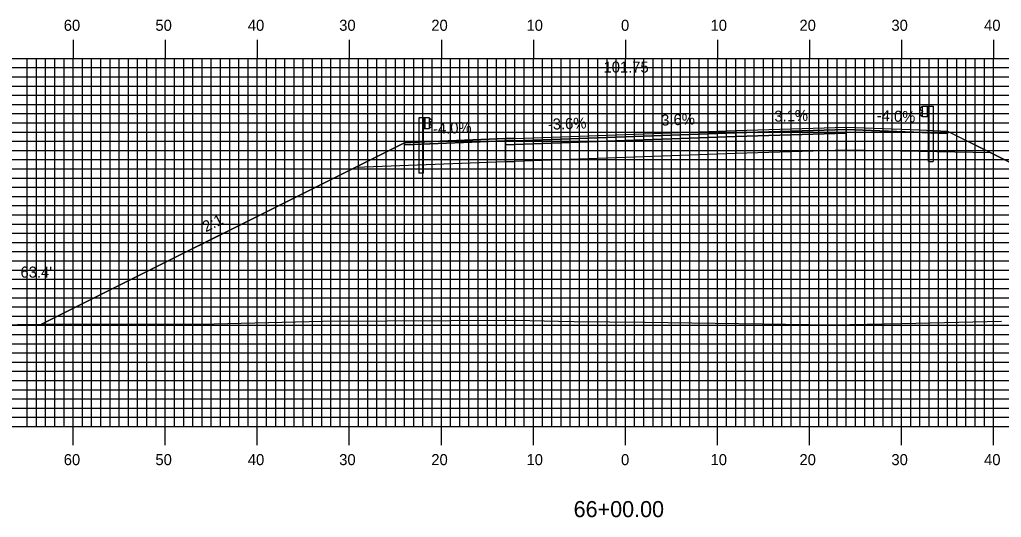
# Model space of a CAD drawing. Extents: x 1759036 to 1759380, y 442591 to 442811.
# Drawn here: x 1759136.3 to 1759243, y 442658.8 to 442712.9 of the extents above; entities that cross this region are included whole.
import ezdxf

# ---------------------------------------------------------------- set-up
doc = ezdxf.new("R2010")
doc.units = 0
for name, color, linetype in [('ANNOTATION', 7, 'Continuous'), ('D_Guardrail_Beam_Lt', 7, 'Continuous'), ('D_Guardrail_Beam_Rt', 7, 'Continuous'), ('D_Roadway_Centerline', 7, 'Continuous'), ('D_Roadway_Centerline_Text', 7, 'Continuous'), ('D_Roadway_Edge_Shoulder', 7, 'Continuous'), ('D_Roadway_Edge_TW', 7, 'Continuous'), ('D_Roadway_Pavement', 7, 'Continuous'), ('D_Roadway_SlopeLines', 7, 'Continuous'), ('D_Roadway_SubGrade', 7, 'Continuous'), ('D_Text_Standard', 7, 'Continuous'), ('H_V ANNOTATION', 7, 'Continuous'), ('MAJOR', 7, 'Continuous'), ('MINOR', 7, 'Continuous'), ('S_Roadway_Centerline', 7, 'Continuous')]:
    doc.layers.add(name, color=color, linetype=linetype)

msp = doc.modelspace()

# ---------------------------------------------------------------- linework, layer by layer
at = {"layer": 'D_Guardrail_Beam_Lt'}
for p, q in [((1759179.71, 442702.21), (1759179.71, 442696.21)), ((1759180.19, 442702.21), (1759179.71, 442702.21)), ((1759180.87, 442702.21), (1759180.19, 442702.21)), ((1759180.19, 442702.21), (1759180.19, 442701.04)), ((1759180.25, 442702.21), (1759180.25, 442701.04)), ((1759180.35, 442702.21), (1759180.35, 442701.04)), ((1759180.87, 442701.04), (1759180.87, 442702.21)), ((1759180.87, 442702.13), (1759180.95, 442702.11)), ((1759180.88, 442701.66), (1759180.88, 442701.59)), ((1759181.11, 442701.86), (1759180.91, 442701.73)), ((1759180.96, 442702.11), (1759181.11, 442702.01)), ((1759180.19, 442701.04), (1759180.87, 442701.04)), ((1759180.21, 442696.21), (1759180.21, 442701.04)), ((1759180.95, 442701.14), (1759180.87, 442701.13)), ((1759180.91, 442701.53), (1759181.11, 442701.39)), ((1759181.11, 442701.25), (1759180.96, 442701.15)), ((1759180.21, 442696.21), (1759179.71, 442696.21))]:
    msp.add_line(p, q, dxfattribs=at)
for centre, major_axis, start_param, end_param in [((1759180.96, 442701.66), (-0.0789, 0), 5.323254, 6.283185), ((1759180.96, 442701.59), (-0.0789, 0), 6.283185, 7.243116), ((1759180.94, 442702.07), (0.0417, 0), 0.959931, 1.376053), ((1759181.06, 442701.93), (0.0877, 0), 5.323254, 7.243116), ((1759180.94, 442701.18), (0.0417, 0), 4.907132, 5.323254), ((1759181.06, 442701.32), (0.0877, 0), 5.323254, 7.243116)]:
    msp.add_ellipse(centre, major_axis=major_axis, ratio=0.995501, start_param=start_param, end_param=end_param, dxfattribs=at)
at = {"layer": 'D_Guardrail_Beam_Rt'}
for p, q in [((1759234.34, 442703.37), (1759234.2, 442703.27)), ((1759234.2, 442703.13), (1759234.39, 442702.99)), ((1759234.39, 442702.8), (1759234.2, 442702.66)), ((1759234.43, 442703.39), (1759234.36, 442703.38)), ((1759234.43, 442703.48), (1759235.12, 442703.48)), ((1759234.43, 442702.31), (1759234.43, 442703.48)), ((1759234.43, 442702.93), (1759234.43, 442702.86)), ((1759234.95, 442703.48), (1759234.95, 442702.31)), ((1759235.06, 442703.48), (1759235.06, 442702.31)), ((1759235.12, 442703.48), (1759235.59, 442703.48)), ((1759235.12, 442703.48), (1759235.12, 442702.31)), ((1759235.59, 442703.48), (1759235.59, 442697.48)), ((1759234.2, 442702.52), (1759234.34, 442702.42)), ((1759234.36, 442702.41), (1759234.43, 442702.39)), ((1759235.12, 442702.31), (1759234.43, 442702.31)), ((1759235.1, 442697.48), (1759235.1, 442702.31)), ((1759235.1, 442697.48), (1759235.59, 442697.48))]:
    msp.add_line(p, q, dxfattribs=at)
for centre, major_axis, start_param, end_param in [((1759234.25, 442703.2), (-0.0877, 0), 5.323254, 7.243116), ((1759234.25, 442702.59), (-0.0877, 0), 5.323254, 7.243116), ((1759234.37, 442703.34), (-0.0417, 0), 4.907132, 5.323254), ((1759234.35, 442702.93), (0.0789, 0), 0, 0.959931), ((1759234.35, 442702.86), (0.0789, 0), 5.323254, 6.283185), ((1759234.37, 442702.45), (-0.0417, 0), 0.959931, 1.376053)]:
    msp.add_ellipse(centre, major_axis=major_axis, ratio=0.995501, start_param=start_param, end_param=end_param, dxfattribs=at)
at = {"layer": 'D_Roadway_Centerline'}
msp.add_lwpolyline([(1759138.72, 442679.79), (1759172.85, 442696.86), (1759178.14, 442699.51), (1759181.14, 442699.63), (1759189.14, 442699.95), (1759190.16, 442699.98), (1759202.16, 442700.41), (1759214.16, 442700.85), (1759226.16, 442701.21), (1759234.16, 442700.89), (1759237.16, 442700.77), (1759241.91, 442698.4), (1759278.21, 442680.25)], dxfattribs=at)
at = {"layer": 'D_Roadway_Edge_Shoulder'}
for points in [[(1759226.16, 442701.21), (1759234.16, 442700.89), (1759234.16, 442700.89), (1759237.16, 442700.77), (1759237.16, 442700.52), (1759226.16, 442700.96)], [(1759189.14, 442699.95), (1759181.14, 442699.63), (1759181.14, 442699.63), (1759178.14, 442699.51), (1759178.14, 442699.26), (1759189.14, 442699.7)]]:
    msp.add_lwpolyline(points, close=True, dxfattribs=at)
at = {"layer": 'D_Roadway_Edge_TW'}
for points in [[(1759190.16, 442699.73), (1759190.16, 442699.98), (1759202.16, 442700.41), (1759214.16, 442700.85), (1759214.16, 442700.6), (1759202.16, 442700.16)], [(1759214.16, 442700.85), (1759226.16, 442701.21), (1759226.16, 442700.96), (1759214.16, 442700.6)], [(1759190.16, 442699.98), (1759189.14, 442699.95), (1759189.14, 442699.7), (1759190.16, 442699.73)]]:
    msp.add_lwpolyline(points, close=True, dxfattribs=at)
at = {"layer": 'D_Roadway_Pavement'}
for points in [[(1759190.16, 442699.32), (1759190.16, 442699.73), (1759202.16, 442700.16), (1759214.16, 442700.6), (1759214.16, 442700.18), (1759202.16, 442699.75)], [(1759214.16, 442700.6), (1759226.16, 442700.96), (1759226.16, 442700.55), (1759214.16, 442700.18)], [(1759190.16, 442699.73), (1759189.14, 442699.7), (1759189.14, 442699.28), (1759190.16, 442699.32)]]:
    msp.add_lwpolyline(points, close=True, dxfattribs=at)
for points in [[(1759226.16, 442700.96), (1759226.16, 442700.55)], [(1759226.16, 442700.96), (1759226.16, 442700.55)], [(1759226.16, 442700.96), (1759226.16, 442700.55)], [(1759226.16, 442700.96), (1759226.16, 442700.55)], [(1759226.16, 442700.96), (1759226.16, 442700.55)], [(1759189.14, 442699.7), (1759189.14, 442699.28)], [(1759189.14, 442699.7), (1759189.14, 442699.28)]]:
    msp.add_lwpolyline(points, dxfattribs=at)
at = {"layer": 'D_Roadway_SlopeLines'}
for points in [[(1759237.16, 442700.77), (1759278.21, 442680.25)], [(1759178.14, 442699.51), (1759138.72, 442679.79)]]:
    msp.add_lwpolyline(points, dxfattribs=at)
at = {"layer": 'D_Roadway_SubGrade'}
for points in [[(1759214.16, 442700.18), (1759226.16, 442700.55), (1759226.16, 442698.71), (1759214.16, 442698.35)], [(1759226.16, 442700.55), (1759226.16, 442700.96), (1759237.16, 442700.52), (1759237.16, 442700.77), (1759241.91, 442698.4), (1759226.16, 442698.71)], [(1759189.14, 442699.28), (1759189.14, 442699.7), (1759178.14, 442699.26), (1759178.14, 442699.51), (1759172.85, 442696.86), (1759189.14, 442697.45)], [(1759190.16, 442697.48), (1759190.16, 442699.32), (1759202.16, 442699.75), (1759214.16, 442700.18), (1759214.16, 442698.35), (1759202.16, 442697.91)], [(1759190.16, 442699.32), (1759189.14, 442699.28), (1759189.14, 442697.45), (1759190.16, 442697.48)]]:
    msp.add_lwpolyline(points, close=True, dxfattribs=at)
at = {"layer": 'MAJOR'}
for p, q in [((1759142.16, 442710.67), (1759142.16, 442708.67)), ((1759152.16, 442710.67), (1759152.16, 442708.67)), ((1759162.16, 442710.67), (1759162.16, 442708.67)), ((1759172.16, 442710.67), (1759172.16, 442708.67)), ((1759182.16, 442710.67), (1759182.16, 442708.67)), ((1759192.16, 442710.67), (1759192.16, 442708.67)), ((1759202.16, 442710.67), (1759202.16, 442708.67)), ((1759212.16, 442710.67), (1759212.16, 442708.67)), ((1759222.16, 442710.67), (1759222.16, 442708.67)), ((1759232.16, 442710.67), (1759232.16, 442708.67)), ((1759242.16, 442710.67), (1759242.16, 442708.67)), ((1759062.16, 442708.67), (1759342.16, 442708.67)), ((1759062.16, 442708.67), (1759342.16, 442708.67)), ((1759142.16, 442668.67), (1759142.16, 442708.67)), ((1759152.16, 442668.67), (1759152.16, 442708.67)), ((1759162.16, 442668.67), (1759162.16, 442708.67)), ((1759172.16, 442668.67), (1759172.16, 442708.67)), ((1759182.16, 442668.67), (1759182.16, 442708.67)), ((1759192.16, 442668.67), (1759192.16, 442708.67)), ((1759202.16, 442668.67), (1759202.16, 442708.67)), ((1759212.16, 442668.67), (1759212.16, 442708.67)), ((1759222.16, 442668.67), (1759222.16, 442708.67)), ((1759232.16, 442668.67), (1759232.16, 442708.67)), ((1759242.16, 442668.67), (1759242.16, 442708.67)), ((1759062.16, 442703.67), (1759342.16, 442703.67)), ((1759062.16, 442698.67), (1759342.16, 442698.67)), ((1759062.16, 442693.67), (1759342.16, 442693.67)), ((1759062.16, 442688.67), (1759342.16, 442688.67)), ((1759062.16, 442683.67), (1759342.16, 442683.67)), ((1759062.16, 442678.67), (1759342.16, 442678.67)), ((1759062.16, 442673.67), (1759342.16, 442673.67)), ((1759062.16, 442668.67), (1759342.16, 442668.67)), ((1759062.16, 442668.67), (1759342.16, 442668.67)), ((1759142.16, 442666.66), (1759142.16, 442668.67)), ((1759152.16, 442666.66), (1759152.16, 442668.67)), ((1759162.16, 442666.66), (1759162.16, 442668.67)), ((1759172.16, 442666.66), (1759172.16, 442668.67)), ((1759182.16, 442666.66), (1759182.16, 442668.67)), ((1759192.16, 442666.66), (1759192.16, 442668.67)), ((1759202.16, 442666.66), (1759202.16, 442668.67)), ((1759212.16, 442666.66), (1759212.16, 442668.67)), ((1759222.16, 442666.66), (1759222.16, 442668.67)), ((1759232.16, 442666.66), (1759232.16, 442668.67)), ((1759242.16, 442666.66), (1759242.16, 442668.67))]:
    msp.add_line(p, q, dxfattribs=at)
at = {"layer": 'MINOR'}
for p, q in [((1759137.16, 442668.67), (1759137.16, 442708.67)), ((1759138.16, 442668.67), (1759138.16, 442708.67)), ((1759139.16, 442668.67), (1759139.16, 442708.67)), ((1759140.16, 442668.67), (1759140.16, 442708.67)), ((1759141.16, 442668.67), (1759141.16, 442708.67)), ((1759143.16, 442668.67), (1759143.16, 442708.67)), ((1759144.16, 442668.67), (1759144.16, 442708.67)), ((1759145.16, 442668.67), (1759145.16, 442708.67)), ((1759146.16, 442668.67), (1759146.16, 442708.67)), ((1759147.16, 442668.67), (1759147.16, 442708.67)), ((1759148.16, 442668.67), (1759148.16, 442708.67)), ((1759149.16, 442668.67), (1759149.16, 442708.67)), ((1759150.16, 442668.67), (1759150.16, 442708.67)), ((1759151.16, 442668.67), (1759151.16, 442708.67)), ((1759153.16, 442668.67), (1759153.16, 442708.67)), ((1759154.16, 442668.67), (1759154.16, 442708.67)), ((1759155.16, 442668.67), (1759155.16, 442708.67)), ((1759156.16, 442668.67), (1759156.16, 442708.67)), ((1759157.16, 442668.67), (1759157.16, 442708.67)), ((1759158.16, 442668.67), (1759158.16, 442708.67)), ((1759159.16, 442668.67), (1759159.16, 442708.67)), ((1759160.16, 442668.67), (1759160.16, 442708.67)), ((1759161.16, 442668.67), (1759161.16, 442708.67)), ((1759163.16, 442668.67), (1759163.16, 442708.67)), ((1759164.16, 442668.67), (1759164.16, 442708.67)), ((1759165.16, 442668.67), (1759165.16, 442708.67)), ((1759166.16, 442668.67), (1759166.16, 442708.67)), ((1759167.16, 442668.67), (1759167.16, 442708.67)), ((1759168.16, 442668.67), (1759168.16, 442708.67)), ((1759169.16, 442668.67), (1759169.16, 442708.67)), ((1759170.16, 442668.67), (1759170.16, 442708.67)), ((1759171.16, 442668.67), (1759171.16, 442708.67)), ((1759173.16, 442668.67), (1759173.16, 442708.67)), ((1759174.16, 442668.67), (1759174.16, 442708.67)), ((1759175.16, 442668.67), (1759175.16, 442708.67)), ((1759176.16, 442668.67), (1759176.16, 442708.67)), ((1759177.16, 442668.67), (1759177.16, 442708.67)), ((1759178.16, 442668.67), (1759178.16, 442708.67)), ((1759179.16, 442668.67), (1759179.16, 442708.67)), ((1759180.16, 442668.67), (1759180.16, 442708.67)), ((1759181.16, 442668.67), (1759181.16, 442708.67)), ((1759183.16, 442668.67), (1759183.16, 442708.67)), ((1759184.16, 442668.67), (1759184.16, 442708.67)), ((1759185.16, 442668.67), (1759185.16, 442708.67)), ((1759186.16, 442668.67), (1759186.16, 442708.67)), ((1759187.16, 442668.67), (1759187.16, 442708.67)), ((1759188.16, 442668.67), (1759188.16, 442708.67)), ((1759189.16, 442668.67), (1759189.16, 442708.67)), ((1759190.16, 442668.67), (1759190.16, 442708.67)), ((1759191.16, 442668.67), (1759191.16, 442708.67)), ((1759193.16, 442668.67), (1759193.16, 442708.67)), ((1759194.16, 442668.67), (1759194.16, 442708.67)), ((1759195.16, 442668.67), (1759195.16, 442708.67)), ((1759196.16, 442668.67), (1759196.16, 442708.67)), ((1759197.16, 442668.67), (1759197.16, 442708.67)), ((1759198.16, 442668.67), (1759198.16, 442708.67)), ((1759199.16, 442668.67), (1759199.16, 442708.67)), ((1759200.16, 442668.67), (1759200.16, 442708.67)), ((1759201.16, 442668.67), (1759201.16, 442708.67)), ((1759203.16, 442668.67), (1759203.16, 442708.67)), ((1759204.16, 442668.67), (1759204.16, 442708.67)), ((1759205.16, 442668.67), (1759205.16, 442708.67)), ((1759206.16, 442668.67), (1759206.16, 442708.67)), ((1759207.16, 442668.67), (1759207.16, 442708.67)), ((1759208.16, 442668.67), (1759208.16, 442708.67)), ((1759209.16, 442668.67), (1759209.16, 442708.67)), ((1759210.16, 442668.67), (1759210.16, 442708.67)), ((1759211.16, 442668.67), (1759211.16, 442708.67)), ((1759213.16, 442668.67), (1759213.16, 442708.67)), ((1759214.16, 442668.67), (1759214.16, 442708.67)), ((1759215.16, 442668.67), (1759215.16, 442708.67)), ((1759216.16, 442668.67), (1759216.16, 442708.67)), ((1759217.16, 442668.67), (1759217.16, 442708.67)), ((1759218.16, 442668.67), (1759218.16, 442708.67)), ((1759219.16, 442668.67), (1759219.16, 442708.67)), ((1759220.16, 442668.67), (1759220.16, 442708.67)), ((1759221.16, 442668.67), (1759221.16, 442708.67)), ((1759223.16, 442668.67), (1759223.16, 442708.67)), ((1759224.16, 442668.67), (1759224.16, 442708.67)), ((1759225.16, 442668.67), (1759225.16, 442708.67)), ((1759226.16, 442668.67), (1759226.16, 442708.67)), ((1759227.16, 442668.67), (1759227.16, 442708.67)), ((1759228.16, 442668.67), (1759228.16, 442708.67)), ((1759229.16, 442668.67), (1759229.16, 442708.67)), ((1759230.16, 442668.67), (1759230.16, 442708.67)), ((1759231.16, 442668.67), (1759231.16, 442708.67)), ((1759233.16, 442668.67), (1759233.16, 442708.67)), ((1759234.16, 442668.67), (1759234.16, 442708.67)), ((1759235.16, 442668.67), (1759235.16, 442708.67)), ((1759236.16, 442668.67), (1759236.16, 442708.67)), ((1759237.16, 442668.67), (1759237.16, 442708.67)), ((1759238.16, 442668.67), (1759238.16, 442708.67)), ((1759239.16, 442668.67), (1759239.16, 442708.67)), ((1759240.16, 442668.67), (1759240.16, 442708.67)), ((1759241.16, 442668.67), (1759241.16, 442708.67)), ((1759062.16, 442707.67), (1759342.16, 442707.67)), ((1759062.16, 442706.67), (1759342.16, 442706.67)), ((1759062.16, 442705.67), (1759342.16, 442705.67)), ((1759062.16, 442704.67), (1759342.16, 442704.67)), ((1759062.16, 442702.67), (1759342.16, 442702.67)), ((1759062.16, 442701.67), (1759342.16, 442701.67)), ((1759062.16, 442700.67), (1759342.16, 442700.67)), ((1759062.16, 442699.67), (1759342.16, 442699.67)), ((1759062.16, 442697.67), (1759342.16, 442697.67)), ((1759062.16, 442696.67), (1759342.16, 442696.67)), ((1759062.16, 442695.67), (1759342.16, 442695.67)), ((1759062.16, 442694.67), (1759342.16, 442694.67)), ((1759062.16, 442692.67), (1759342.16, 442692.67)), ((1759062.16, 442691.67), (1759342.16, 442691.67)), ((1759062.16, 442690.67), (1759342.16, 442690.67)), ((1759062.16, 442689.67), (1759342.16, 442689.67)), ((1759062.16, 442687.67), (1759342.16, 442687.67)), ((1759062.16, 442686.67), (1759342.16, 442686.67)), ((1759062.16, 442685.67), (1759342.16, 442685.67)), ((1759062.16, 442684.67), (1759342.16, 442684.67)), ((1759062.16, 442682.67), (1759342.16, 442682.67)), ((1759062.16, 442681.67), (1759342.16, 442681.67)), ((1759062.16, 442680.67), (1759342.16, 442680.67)), ((1759062.16, 442679.67), (1759342.16, 442679.67)), ((1759062.16, 442677.67), (1759342.16, 442677.67)), ((1759062.16, 442676.67), (1759342.16, 442676.67)), ((1759062.16, 442675.67), (1759342.16, 442675.67)), ((1759062.16, 442674.67), (1759342.16, 442674.67)), ((1759062.16, 442672.67), (1759342.16, 442672.67)), ((1759062.16, 442671.67), (1759342.16, 442671.67)), ((1759062.16, 442670.67), (1759342.16, 442670.67)), ((1759062.16, 442669.67), (1759342.16, 442669.67))]:
    msp.add_line(p, q, dxfattribs=at)
at = {"layer": 'S_Roadway_Centerline'}
msp.add_lwpolyline([(1759062.16, 442679.65), (1759065.62, 442679.65), (1759073.13, 442679.7), (1759082.26, 442679.88), (1759092.59, 442679.35), (1759097.73, 442679.35), (1759106.71, 442679.64), (1759112.82, 442679.59), (1759126.49, 442679.67), (1759130.49, 442679.66), (1759133.22, 442679.71), (1759141.87, 442679.84), (1759152.59, 442679.78), (1759153.87, 442679.8), (1759155.98, 442679.79), (1759169.27, 442680.13), (1759190.2, 442680.24), (1759194.89, 442680.1), (1759196.6, 442680.09), (1759204.26, 442680.01), (1759224.65, 442679.73), (1759232.15, 442679.87), (1759243.01, 442680.13)], dxfattribs=at)

# ---------------------------------------------------------------- texts
at = {"layer": 'ANNOTATION'}
for s, rotation, p in [('3.6%', 2.0618, (1759206.07, 442701.36)), ('3.1%', 1.755, (1759218.36, 442701.78)), ('-4.0%', 357.7094, (1759229.45, 442701.88)), ('-4.0%', 2.2906, (1759181.28, 442700.43)), ('-3.6%', 2.0618, (1759193.75, 442700.91)), ('2:1', 26.5651, (1759156.58, 442689.76))]:
    msp.add_text(s, height=1.2, rotation=rotation, dxfattribs=at).set_placement(p)
at = {"layer": 'D_Roadway_Centerline'}
for s in ['C', 'L']:
    msp.add_text(s, height=0.0146, dxfattribs=at).set_placement((1759202.16, 442700.41))
at = {"layer": 'D_Roadway_Centerline_Text'}
msp.add_text('101.75', height=1.2, dxfattribs=at).set_placement((1759199.78, 442707.13))
at = {"layer": 'D_Text_Standard'}
msp.add_text("63.4'", height=1.2, dxfattribs=at).set_placement((1759136.43, 442684.85))
at = {"layer": 'H_V ANNOTATION'}
for s, height, p in [('60', 1.2, (1759141.13, 442711.67)), ('50', 1.2, (1759151.09, 442711.67)), ('40', 1.2, (1759161.13, 442711.67)), ('30', 1.2, (1759171.06, 442711.67)), ('20', 1.2, (1759181.07, 442711.67)), ('10', 1.2, (1759191.41, 442711.67)), ('0', 1.2, (1759201.68, 442711.67)), ('10', 1.2, (1759211.41, 442711.67)), ('20', 1.2, (1759221.07, 442711.67)), ('30', 1.2, (1759231.06, 442711.67)), ('40', 1.2, (1759241.13, 442711.67)), ('60', 1.2, (1759141.13, 442664.47)), ('50', 1.2, (1759151.09, 442664.47)), ('40', 1.2, (1759161.13, 442664.47)), ('30', 1.2, (1759171.06, 442664.47)), ('20', 1.2, (1759181.07, 442664.47)), ('10', 1.2, (1759191.41, 442664.47)), ('0', 1.2, (1759201.68, 442664.47)), ('10', 1.2, (1759211.41, 442664.47)), ('20', 1.2, (1759221.07, 442664.47)), ('30', 1.2, (1759231.06, 442664.47)), ('40', 1.2, (1759241.13, 442664.47)), ('66+00.00', 1.75, (1759196.53, 442658.82))]:
    msp.add_text(s, height=height, dxfattribs=at).set_placement(p)

doc.saveas('drawing.dxf')
